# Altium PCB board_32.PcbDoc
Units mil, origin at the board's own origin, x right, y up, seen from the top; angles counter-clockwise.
Board outline 3248.03 x 3149.61 mil, 2 copper layers (Top Layer, Bottom Layer); 42 components, 39 nets, 152 pads, 6 vias.
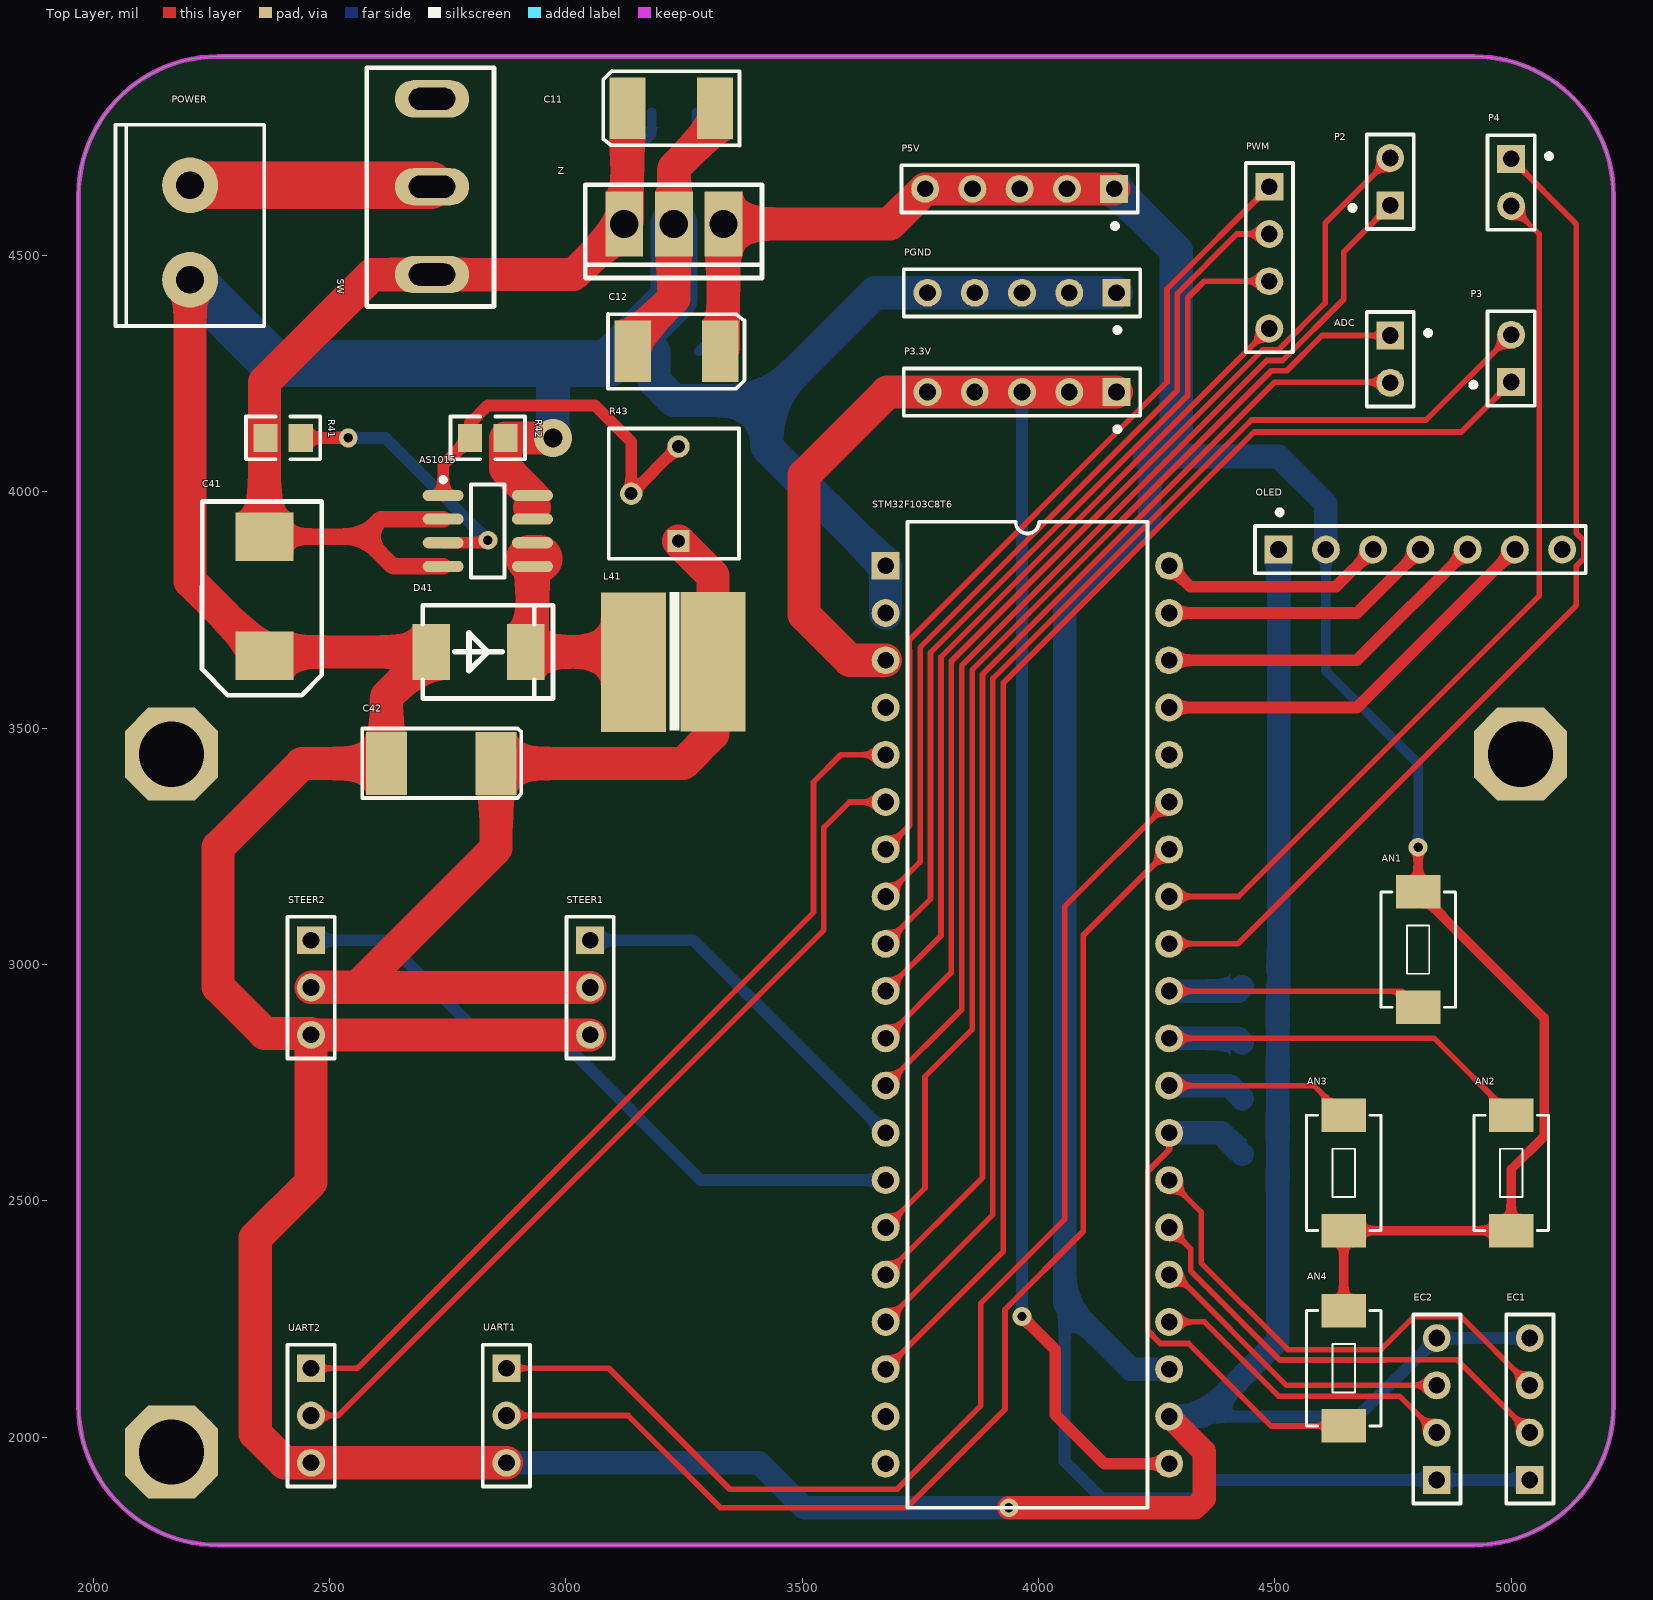
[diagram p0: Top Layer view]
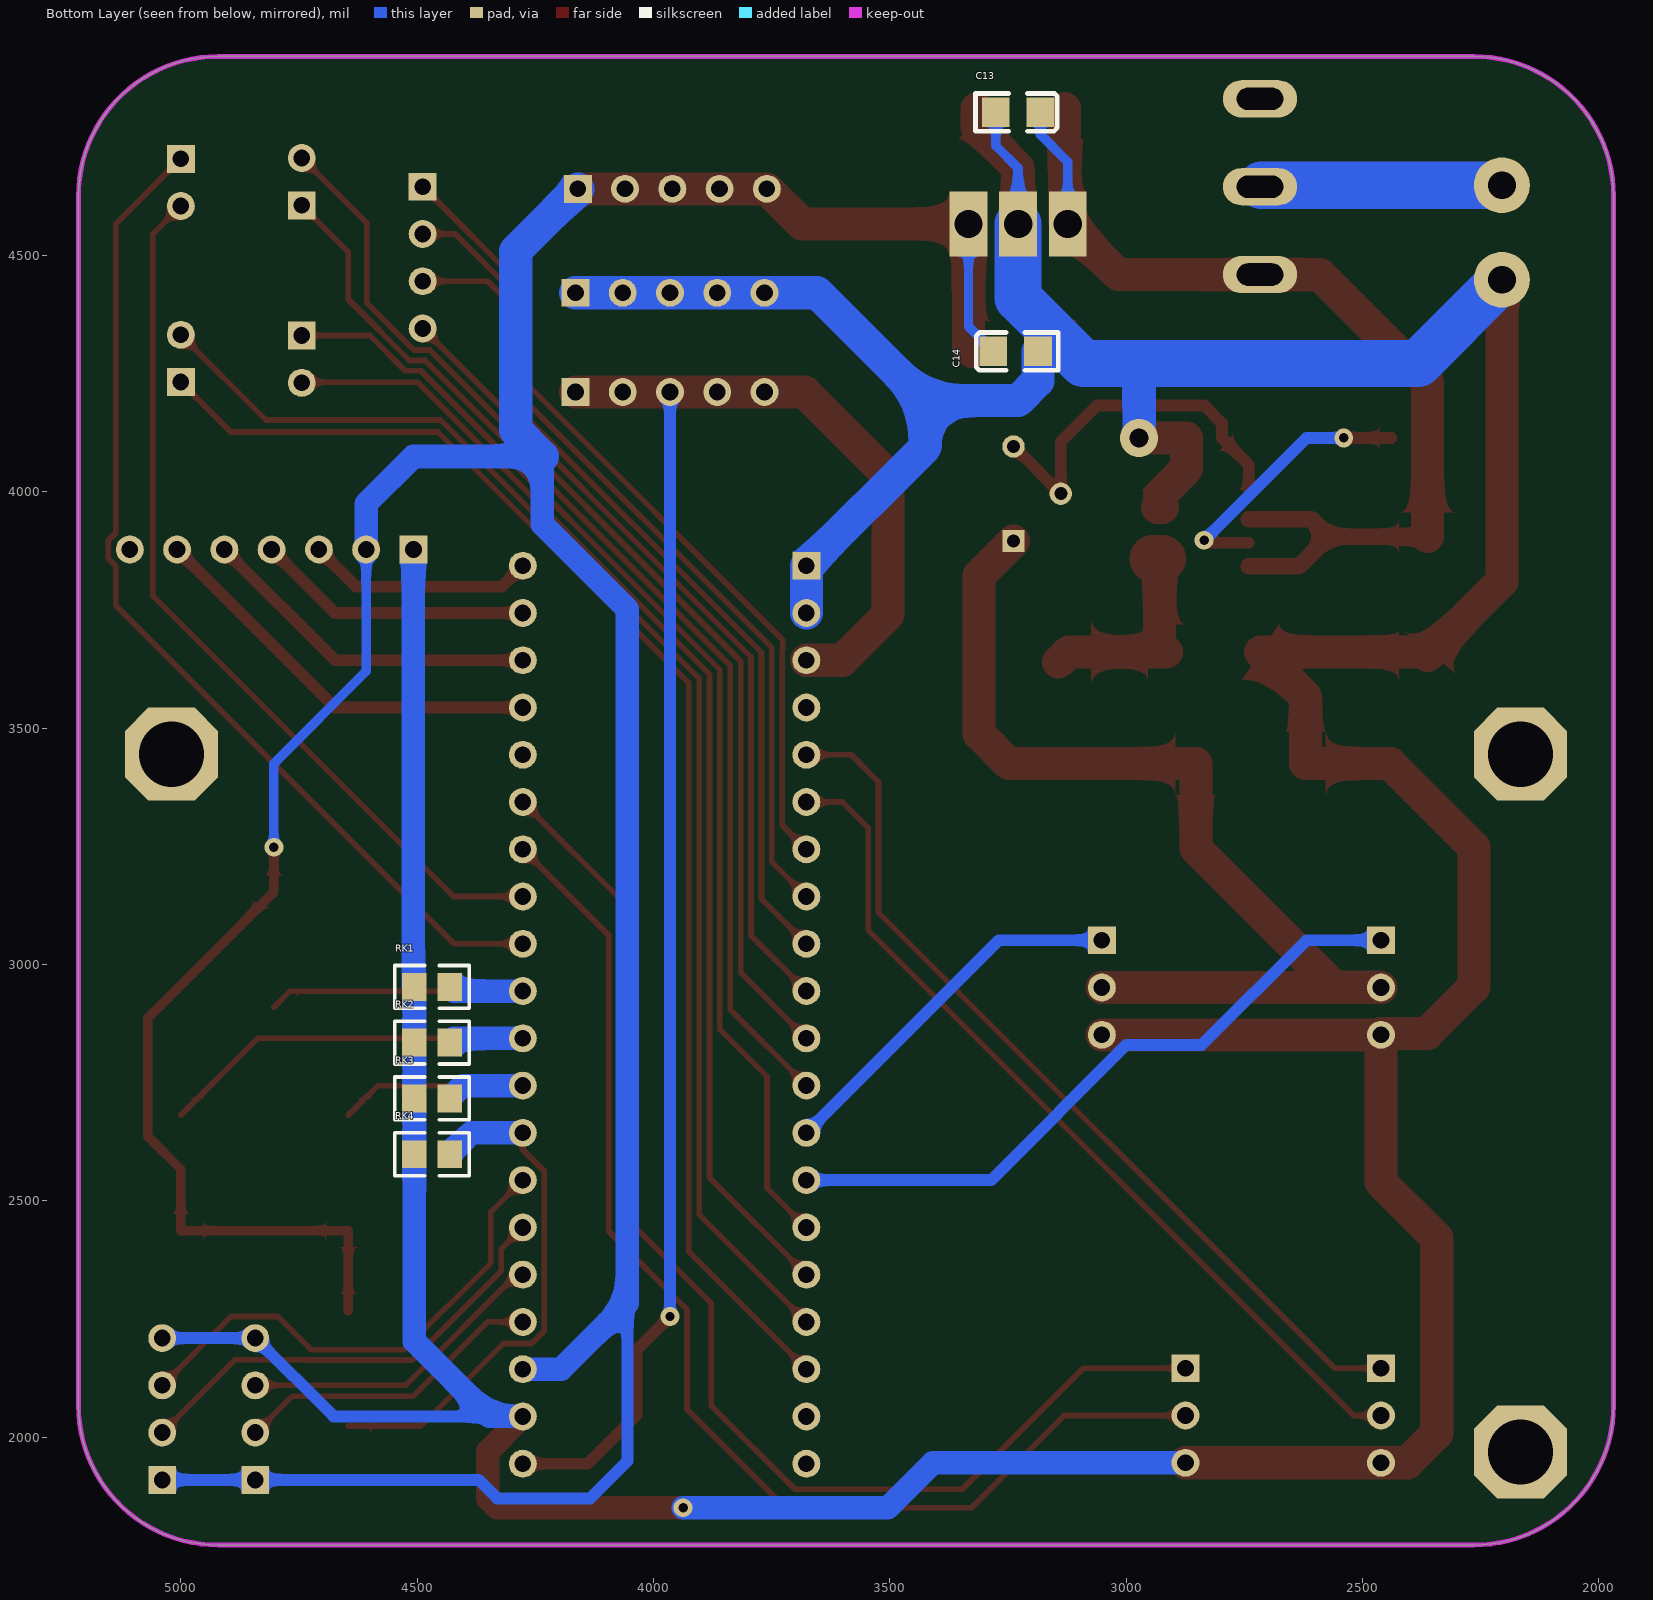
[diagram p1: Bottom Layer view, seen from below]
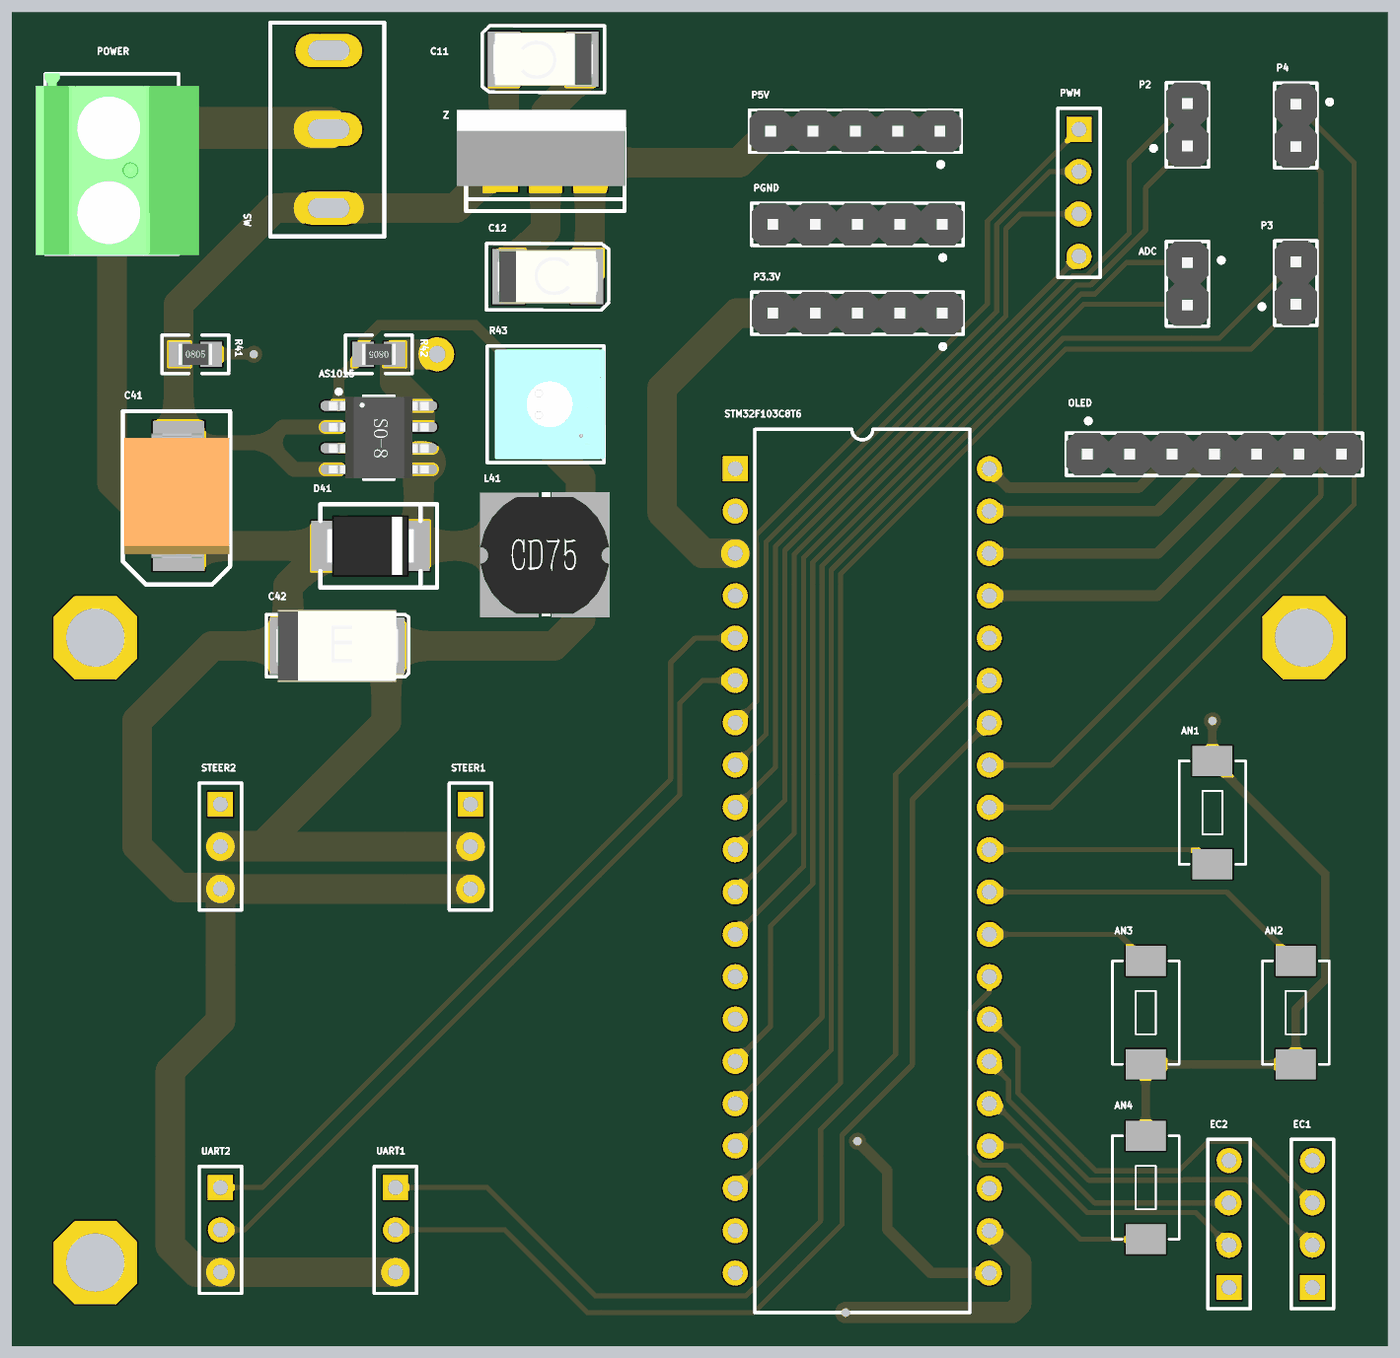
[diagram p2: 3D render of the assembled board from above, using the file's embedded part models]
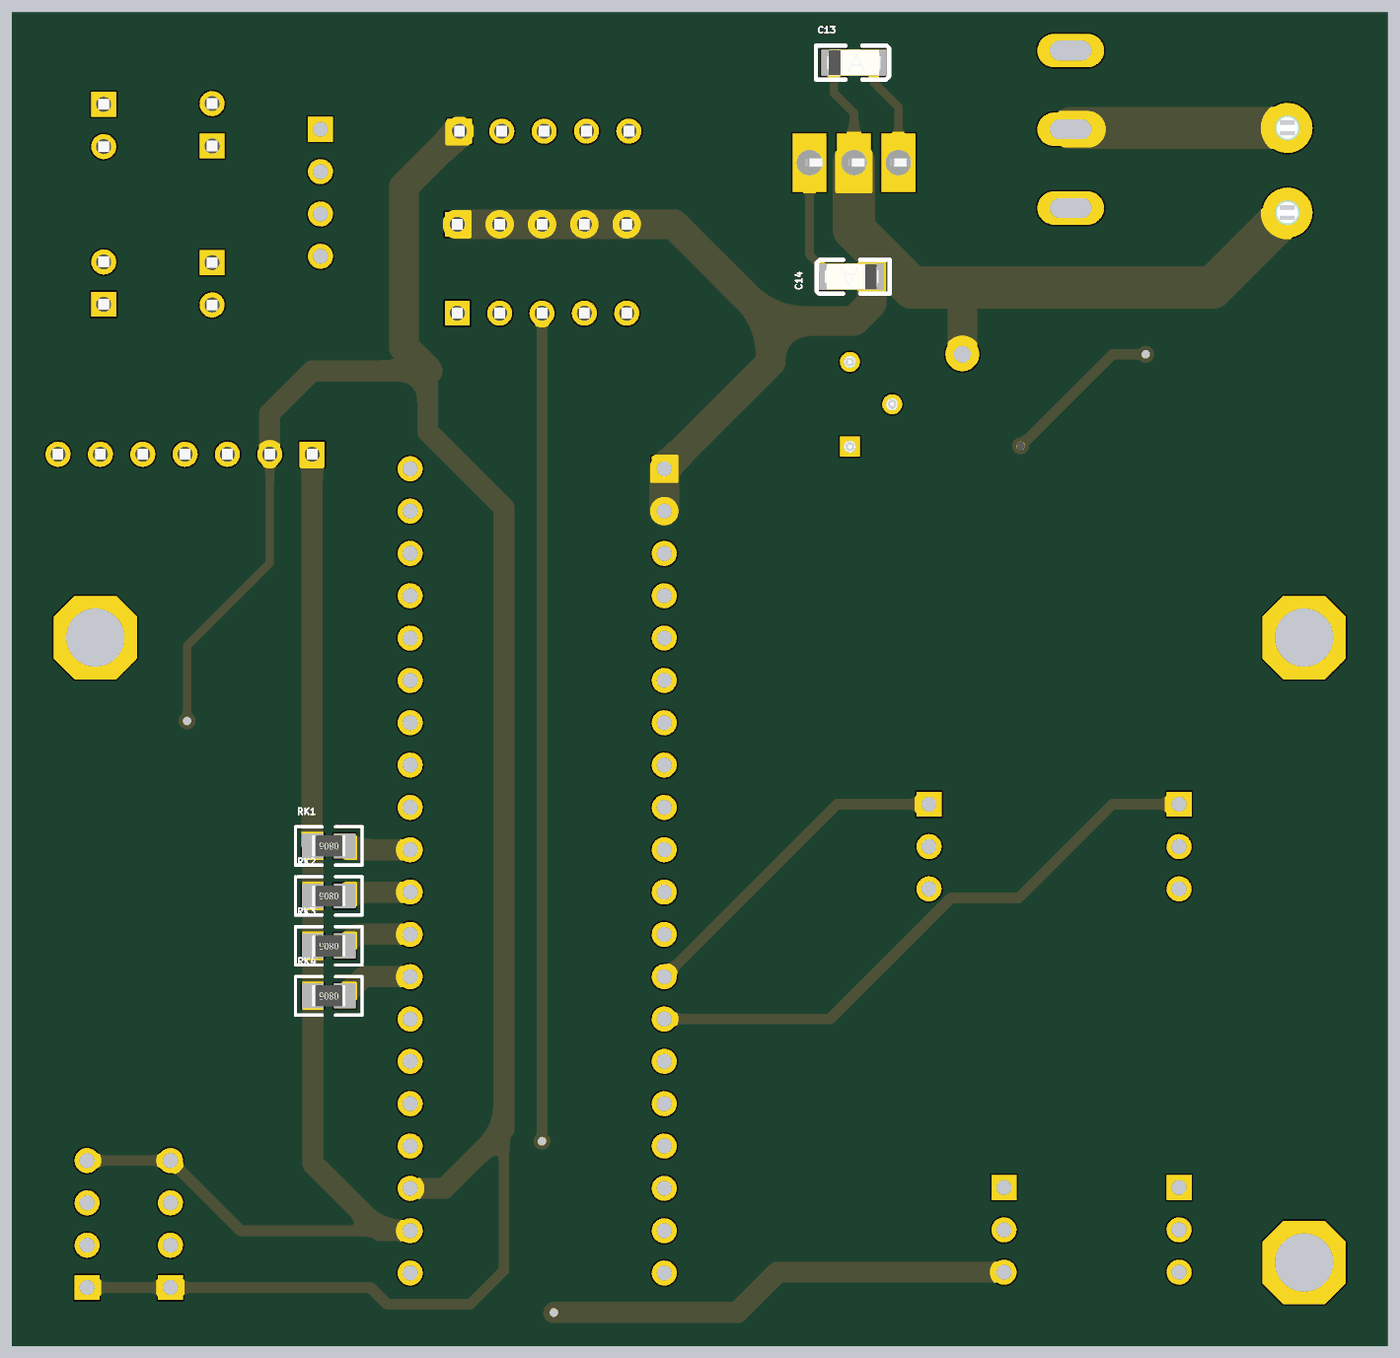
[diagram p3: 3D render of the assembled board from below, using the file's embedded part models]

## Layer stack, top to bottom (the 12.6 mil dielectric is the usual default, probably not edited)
Top Solder: solder mask 0.4, Solder Resist, Dk 3.5
Top Layer: signal copper 1.4
Dielectric 1: dielectric 12.6, FR-4, Dk 4.8
Bottom Layer: signal copper 1.4
Bottom Solder: solder mask 0.4, Solder Resist, Dk 3.5

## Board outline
1968.5,2066.93 1968.5,4625.98 cw(c2263.78,4625.98) 2263.78,4921.26 4921.26,4921.26 cw(c4921.26,4625.98) 5216.54,4625.98 5216.54,2066.93 cw(c4921.26,2066.93) 4921.26,1771.65 2263.78,1771.65 cw(c2263.78,2066.93)

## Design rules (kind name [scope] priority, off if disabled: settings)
Clearance [All] p1: gap=8
Height [All] p1 off: minheight=0 maxheight=1000 prefheight=500
HoleSize [All] p1: absolutevalues=TRUE maxlimit=300 minlimit=1 maxpercent=80.000 minpercent=20.000
PolygonConnect [All] p1: connectstyle=Relief reliefconductorwidth=10 reliefentries=4 polygonreliefangle="90 Angle" airgapwidth=10
RoutingVias [All] p1: holewidth=28 width=50 viastyle="Through Hole" minholewidth=15 minwidth=30 maxholewidth=40 maxwidth=80
SilkToSilkClearance [All] p1 off: silktosilkclearance=10
SilkToSolderMaskClearance [IsPad] p1 off: minsilkscreentomaskgap=10 clearancetoexposedcopper=TRUE
SolderMaskExpansion [All] p1: expansion=4
Width [All] p1: maxlimit=200 minlimit=10 preferedwidth=12
26 further rules are at their usual default settings.

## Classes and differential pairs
component class board_32: ADC AN1 AN2 AN3 AN4 AS1015 C11 C12 C13 C14 C41 C42 D41 EC1 EC2 L41 OLED P2 P3 P3.3V P4 P5V PGND POWER PWM R41 R42 R43 RK1 RK2 RK3 RK4 STEER1 STEER2 STM32F103C8T6 SW UART1 UART2 Z

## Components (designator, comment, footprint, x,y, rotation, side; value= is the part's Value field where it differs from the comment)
ADC "Header 2" HDR1X2 4744.09,4330.71 r270 top
AN1 "Button" SMT4*6.2*4 4803.15,3031.5 r90 top
AN2 "Button" SMT4*6.2*4 5000,2559.06 r270 top
AN3 "Button" SMT4*6.2*4 4645.67,2559.06 r270 top
AN4 "Button" SMT4*6.2*4 4645.67,2145.67 r90 top
AS1015 "AS1015" SOP-8N 2834.65,3917.32 r0 top locked
C11 "Cap Tan C" TAN-C-6032 3222.72,4811.46 r180 top locked
C12 "Cap Tan C" TAN-C-6032 3233.7,4297.4 r0 top locked
C13 "Cap Tan A" TAN-A-3216 3228.35,4803.15 r180 bottom locked
C14 "Cap Tan A" TAN-A-3216 3233.7,4297.4 r0 bottom locked
C41 "Cap Tan E" C7361 2362.2,3779.53 r90 top locked
C42 "Cap Tan E" TAN-E-7361 2736.22,3425.2 r0 top locked
D41 "1N5824" SMB 2814.96,3661.42 r0 top locked
EC1 "Header 4" HDR1X4 5039.37,1909.45 r90 top
EC2 "Header 4" HDR1X4 4842.52,1909.45 r90 top
L41 "Inductor" CD75NP 3228.35,3641.73 r0 top locked
OLED "Header 7" HDR1X7 4507.87,3877.95 r0 top
P2 "Header 2" HDR1X2 4744.09,4606.3 r90 top
P3 "Header 2" HDR1X2 5000,4232.28 r90 top
P3.3V "Header 5" HDR1X5 4164.96,4211.26 r180 top locked
P4 "Header 2" HDR1X2 5000,4704.72 r270 top
P5V "Header 5" HDR1X5 4159.96,4641.26 r180 top locked
PGND "Header 5" HDR1X5 4164.96,4421.26 r180 top locked
POWER "Header 2" 2PIN-5.08A 2204.72,4448.82 r90 top locked
PWM "Header 4" HDR1X4 4488.19,4645.67 r270 top
R41 "Resistor Chip 0805" R0805 2401.57,4114.17 r0 top locked
R42 "Resistor Chip 0805" R0805 2834.65,4114.17 r180 top locked
R43 "RPot" VR_B1 3248.03,3996.06 r90 top locked
RK1 "Resistor Chip 0805" R0805 4468.5,2952.76 r0 bottom
RK2 "Resistor Chip 0805" R0805 4468.5,2834.65 r0 bottom
RK3 "Resistor Chip 0805" R0805 4468.5,2716.54 r0 bottom
RK4 "Resistor Chip 0805" R0805 4468.5,2598.43 r0 bottom
STEER1 "Header 3" HDR1X3 3051.18,3051.18 r270 top locked
STEER2 "Header 3" HDR1X3 2460.63,3051.18 r270 top locked
STM32F103C8T6 "stm32c8t6mini" DIP-40 3976.38,2893.7 r270 top
SW "SW" SW-TO3 2716.54,4645.67 r0 top locked
UART1 "Header 3" HDR1X3 2874.02,2145.67 r270 top
UART2 "Header 3" HDR1X3 2460.63,2145.67 r270 top
Z "LM2940" TO-220E 3228.35,4566.93 r180 top locked
? "Comment" "Screw hexagon 3mm" 2165.35,3444.88 r0 top
? "Comment" "Screw hexagon 3mm" 5019.69,3444.88 r0 top
? "Comment" "Screw hexagon 3mm" 2165.35,1968.5 r0 top

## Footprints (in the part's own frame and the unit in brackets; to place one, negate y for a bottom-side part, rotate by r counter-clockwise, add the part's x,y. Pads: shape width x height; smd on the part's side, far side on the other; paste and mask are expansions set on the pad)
2PIN-5.08A [mm]
  round 3 hole 1.5: 1(0,0) 2(5.08,0)
  silkscreen extent -2.49,-3.99 8.33,4.01, body extent -2.54,-5.2 8.36,4.6, height 14.2
C7361 [mm] "D型"
  rect 2.6x3.1 smd: 1(-3.202,0.007) 2(3.198,0.007)
  silkscreen extent -5.33,-3.07 5.08,3.36, body extent -3.75,-3.05 3.75,3.25, height 3.45
CD75NP [mm]
  rect 3.5x7.5 smd mask+0: 1(-2.174,-0.051) 2(2.101,-0.028)
  silkscreen extent -0.23,-3.72 0.29,3.73, body extent -3.91,-3.57 3.83,3.43, height 5
DIP-40 [mm] "51单片机"
  rect 1.5x1.5 hole 0.9: 1(-24.13,-7.62)
  round 1.5 hole 0.9: 2(-21.59,-7.62) 3(-19.05,-7.62) 4(-16.51,-7.62) 5(-13.97,-7.62) 6(-11.43,-7.62) 7(-8.89,-7.62) 8(-6.35,-7.62) 9(-3.81,-7.62) 10(-1.27,-7.62) 11(1.27,-7.62) 12(3.81,-7.62) 13(6.35,-7.62) 14(8.89,-7.62) 15(11.43,-7.62) 16(13.97,-7.62) 17(16.51,-7.62) 18(19.05,-7.62) 19(21.59,-7.62) 20(24.13,-7.62) 21(24.13,7.62) 22(21.59,7.62) 23(19.05,7.62) 24(16.51,7.62) 25(13.97,7.62) 26(11.43,7.62) 27(8.89,7.62) 28(6.35,7.62) 29(3.81,7.62) 30(1.27,7.62) 31(-1.27,7.62) 32(-3.81,7.62) 33(-6.35,7.62) 34(-8.89,7.62) 35(-11.43,7.62) 36(-13.97,7.62) 37(-16.51,7.62) 38(-19.05,7.62) 39(-21.59,7.62) 40(-24.13,7.62)
  silkscreen extent -26.5,-6.45 26.5,6.45
HDR1X2 [mm] "Connector; Header; 2 Position"
  rect 1.5x1.5 hole 0.9: 1(0,0)
  round 1.5 hole 0.9: 2(2.54,0)
  silkscreen extent -1.27,-1.27 3.81,2.17, body extent -1.27,-1.27 3.81,1.27, height 8.54
HDR1X3 [mm] "Connector; Header; 3 Position"
  rect 1.5x1.5 hole 0.9: 1(0,0)
  round 1.5 hole 0.9: 2(2.54,0) 3(5.08,0)
  silkscreen extent -1.27,-1.27 6.35,1.27
HDR1X4 [mm] "Connector; Header; 4 Position"
  rect 1.5x1.5 hole 0.9: 1(0,0)
  round 1.5 hole 0.9: 2(2.54,0) 3(5.08,0) 4(7.62,0)
  silkscreen extent -1.27,-1.27 8.89,1.27
HDR1X5 [mm] "Connector; Header; 5 Position"
  rect 1.5x1.5 hole 0.9: 1(0,0)
  round 1.5 hole 0.9: 2(2.54,0) 3(5.08,0) 4(7.62,0) 5(10.16,0)
  silkscreen extent -1.27,-1.27 11.43,2.14, body extent -1.27,-1.27 11.43,1.27, height 8.54
HDR1X7 [mm] "Connector; Header; 7 Position"
  rect 1.5x1.5 hole 0.9: 1(0,0)
  round 1.5 hole 0.9: 2(2.54,0) 3(5.08,0) 4(7.62,0) 5(10.16,0) 6(12.7,0) 7(15.24,0)
  silkscreen extent -1.27,-1.27 16.51,2.14, body extent -1.27,-1.27 16.51,1.27, height 8.54
R0805 [mm]
  rect 1.3x1.5 smd: 1(-0.95,0) 2(0.95,0)
  silkscreen extent -2,-1.15 2,1.15, body extent -1,-0.63 1,0.63, height 0.55
"Screw hexagon 3mm" [mm] "screw hole"
  oct 5x5 hole 3.5: 1(0,0)
SMB [mm]
  rect 2x3 smd: 1(-2.54,0) 2(2.54,0)
  silkscreen extent -3,-2.5 4,2.5, body extent -2.65,-1.85 2.65,1.85, height 2.2
SMT4*6.2*4 [mm]
  rect 1.8x2.4 smd: 1(-3.1,0) 2(3.1,0)
  silkscreen extent -3.1,-2 3.1,2, body extent -3.05,-1.95 3.05,1.75, height 2.5
SOP-8N [mm] "SOIC, 8-Leads, Body 4.9x3.9mm, Pitch 1.27mm, IPC Medium Density"
  oval 2.2x0.6 smd: 1(-2.4,1.905) 2(-2.4,0.635) 3(-2.4,-0.635) 4(-2.4,-1.905) 5(2.4,-1.905) 6(2.4,-0.635) 7(2.4,0.635) 8(2.4,1.905)
  silkscreen extent -2.52,-2.5 0.9,2.88, body extent -3,-2.45 3,2.45, height 1.7
SW-TO3 [mm]
  oval 4x2 hole 1.2 slot 2.5 at 0 deg: 1(0,-4.724) 2(0,0) 3(0,4.724)
  silkscreen extent -3.5,-6.43 3.33,6.39, body extent -3.43,-6.36 3.43,6.35, height 28.55
TAN-A-3216 [mm]
  rect 1.5x1.6 smd: 1(-1.2,0) 2(1.2,0)
  silkscreen extent -2.29,-1.02 2.11,1.02, body extent -1.6,-0.8 1.6,0.8, height 1.6
TAN-C-6032 [mm]
  rect 1.95x3.3 smd: 1(-2.35,0) 2(2.35,0)
  silkscreen extent -3.68,-2.01 3.66,2, body extent -3,-1.6 3,1.6, height 2.6
TAN-E-7361 [mm]
  rect 2.2x3.4 smd: 1(-2.95,0) 2(2.95,0)
  silkscreen extent -4.24,-1.85 4.29,1.88, body extent -3.65,-2.15 3.65,2.15, height 4.1
TO-220E [mil]
  rect 80x138 hole 60: 1(105,0) 2(0,0) 3(-105,0)
  silkscreen extent -186,-83 188,114, body extent -190,-125 210,55, height 730
VR_B1 [mm] "Potentiometer; 3 Leads"
  rect 1.2x1.2 hole 0.7: 1(-2.54,0.254)
  round 1.2 hole 0.7: 2(0,2.794) 3(2.54,0.254)
  silkscreen extent -3.5,-3 3.5,4, body extent -3.3,-3.05 3.3,3.55, height 4.4

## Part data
ADC P2 P3 P4 POWER: "Header, 2-Pin"
C11 C12 C13 C14 C41 C42: "Polarized Capacitor (Radial)"
D41: library part 1N4007, "1.0 Ampere General Purpose Rectifier"
EC1 EC2 PWM: "Header, 4-Pin"
OLED: "Header, 7-Pin"
P3.3V P5V PGND: "Header, 5-Pin"
R41 R42 RK1 RK2 RK3 RK4: "Resistor"
R43: "精密可调电阻"
STEER1 STEER2 UART1 UART2: "Header, 3-Pin"
SW: library part 开关三脚大电流
Z: "SOT-223"

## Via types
v1: diameter 40, hole 20, Top Layer to Bottom Layer, tented both sides, 5 vias
v2: diameter 80, hole 40, Top Layer to Bottom Layer, 1 vias

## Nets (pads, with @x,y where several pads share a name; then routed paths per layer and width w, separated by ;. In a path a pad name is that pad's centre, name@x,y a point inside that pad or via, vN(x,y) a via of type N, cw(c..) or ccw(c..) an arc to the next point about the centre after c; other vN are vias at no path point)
3.3V: P3.3V.1 P3.3V.2 P3.3V.3 P3.3V.4 P3.3V.5 STM32F103C8T6.3 STM32F103C8T6.21 | length 3718.6
  Top Layer w25: v1(3964.96,2255.12) 4035.43,2184.65 4035.43,2047.24 4138.98,1943.7 STM32F103C8T6.21
  Top Layer w70: STM32F103C8T6.3 3600.39,3643.7 3503.94,3740.16 3503.94,4035.43 3679.76,4211.26 P3.3V.5 P3.3V.4 P3.3V.3 P3.3V.2 P3.3V.1
  Bottom Layer w25: v1(3964.96,2255.12) P3.3V.3
5V: AN1.2 AN2.2 AN3.2 AN4.2 C12.2 C14.2 EC1.1 EC2.1 OLED.2 P5V.1 P5V.2 P5V.3 P5V.4 P5V.5 STM32F103C8T6.23 Z.3 | length 8274.1
  Top Layer w20: AN4.2 AN3.2 AN2.2 5000,2566.61 5069.74,2636.35 5069.74,2886.95 AN1.2 v1(4803.15,3248.03)
  Top Layer w70: C12.2 3333.35,4304.53 Z.3 3685.63,4566.93 P5V.5 P5V.4 P5V.3 P5V.2 P5V.1
  Bottom Layer w20: C14.2 3333.35,4349.8 Z.3 ; OLED.2 4607.87,3620.47 4803.15,3425.2 v1(4803.15,3248.03)
  Bottom Layer w25: 4055.12,2283.46 4055.12,1948.82 4133.86,1870.08 4330.71,1870.08 4370.08,1909.45 EC2.1 EC1.1
  Bottom Layer w50: STM32F103C8T6.23 4194.88,2143.7 4055.12,2283.46 4055.12,3751.5 4234.96,3931.34 4234.96,4074.8 4507.87,4074.8 4607.87,3974.8 OLED.2
  Bottom Layer w70: P5V.1 4291.34,4509.88 4291.34,4131.18 4234.96,4074.8
6V: C42.2 L41.2 R43.1 STEER1.2 STEER2.2 | length 2206.4
  Top Layer w70: STEER1.2 STEER2.2 2462.2,2952.76 2559.06,2952.76 2852.36,3246.06 C42.2 3248.03,3425.2 3311.05,3488.21 L41.2 3311.05,3823.05 R43.1
A4: P2.1 STM32F103C8T6.12 | length 2324.4
  Top Layer w12: STM32F103C8T6.12 3837.38,2904.7 3837.38,3632.63 4482.89,4278.14 4516.16,4278.14 4645.67,4407.65 4645.67,4507.87 P2.1
A5: P2.2 STM32F103C8T6.11 | length 2324.4
  Top Layer w12: STM32F103C8T6.11 3815.38,2982.7 3815.38,3641.75 4473.77,4300.14 4507.05,4300.14 4606.3,4399.39 4606.3,4568.5 P2.2
A11: P4.2 STM32F103C8T6.33 | length 1895.7
  Top Layer w12: STM32F103C8T6.33 4423.23,3143.7 5059.06,3779.53 5059.06,4545.67 P4.2
A12: P4.1 STM32F103C8T6.32 | length 2172.9
  Top Layer w12: STM32F103C8T6.32 4421.65,3043.7 5137.8,3759.84 5137.8,3843.49 5153.4,3859.09 5153.4,3896.81 5137.8,3912.42 5137.8,4566.93 P4.1
ADC1: ADC.1 STM32F103C8T6.15 | length 2433.1
  Top Layer w12: STM32F103C8T6.15 3759.84,2527.17 3759.84,2762.78 3859.38,2862.32 3859.38,3623.16 4492.36,4256.14 4525.27,4256.14 4599.84,4330.71 ADC.1
ADC2: ADC.2 STM32F103C8T6.16 | length 2474.7
  Top Layer w12: STM32F103C8T6.16 3881.38,2548.7 3881.38,3614.04 4499.62,4232.28 4742.52,4232.28 ADC.2
C14: P3.1 STM32F103C8T6.18 | length 2893.5
  Top Layer w12: STM32F103C8T6.18 3925.38,2392.7 3925.38,3595.82 4456.12,4126.56 4894.28,4126.56 P3.1
C15: P3.2 STM32F103C8T6.17 | length 2853.2
  Top Layer w12: STM32F103C8T6.17 3903.38,2470.7 3903.38,3604.93 4450.4,4151.96 4819.67,4151.96 P3.2
D0: OLED.3 STM32F103C8T6.40 | length 482.5
  Top Layer w25: STM32F103C8T6.40 4320.87,3799.21 4629.13,3799.21 OLED.3
D1: STEER1.1 STM32F103C8T6.13 | length 794
  Bottom Layer w25: STEER1.1 3268.9,3051.18 STM32F103C8T6.13
D2: STEER2.1 STM32F103C8T6.14 | length 1426
  Bottom Layer w25: STEER2.1 2618.11,3051.18 2839.66,2829.63 2999.15,2829.63 3285.08,2543.7 STM32F103C8T6.14
DC: OLED.6 STM32F103C8T6.37 | length 869.9
  Top Layer w25: STM32F103C8T6.37 4673.62,3543.7 OLED.6
DI: OLED.4 STM32F103C8T6.39 | length 587.1
  Top Layer w25: STM32F103C8T6.39 4673.62,3743.7 OLED.4
ECA1: EC1.3 STM32F103C8T6.27 | length 1063.8
  Top Layer w12: STM32F103C8T6.27 4343.91,2476.17 4343.91,2368.69 4527.56,2185.04 4724.41,2185.04 4794.35,2254.98 4893.84,2254.98 EC1.3
ECA2: EC2.3 STM32F103C8T6.25 | length 663.2
  Top Layer w12: STM32F103C8T6.25 4290.16,2343.7 4524.41,2109.45 EC2.3
ECB1: EC1.2 STM32F103C8T6.26 | length 971
  Top Layer w12: STM32F103C8T6.26 4321.91,2398.17 4321.91,2351.32 4510.19,2163.04 4733.52,2163.04 4734.4,2163.92 4884.9,2163.92 EC1.2
ECB2: EC2.2 STM32F103C8T6.24 | length 663.2
  Top Layer w12: STM32F103C8T6.24 4350.79,2243.7 4507.87,2086.61 4763.78,2086.61 4840.94,2009.45 EC2.2
GND: AS1015.7 AS1015.8 C11.1 C12.1 C13.1 C14.1 C41.1 C42.1 D41.1 EC1.4 EC2.4 OLED.1 PGND.1 PGND.2 PGND.3 PGND.4 PGND.5 POWER.1 R42.1 RK1.2 RK2.2 RK3.2 RK4.2 STEER1.3 STEER2.3 STM32F103C8T6.1 STM32F103C8T6.2 STM32F103C8T6.22 UART1.3 UART2.3 Z.2 | length 13232
  Top Layer w50: v1(3937.01,1850.39) 4330.71,1850.39 4350.39,1870.08 4350.39,1969.69 STM32F103C8T6.22
  Top Layer w70: POWER.1 2204.72,3810.67 C41.1 2369.88,3661.42 D41.1 2620.08,3566.54 C42.1 2440.94,3425.2 2263.78,3248.03 2263.78,2952.76 2362.2,2854.33 2460.63,2854.33 STEER2.3 ; UART1.3 UART2.3 2404.72,1945.67 2342.52,2007.87 2342.52,2421.26 2460.63,2539.37 STEER2.3 ; 2923.23,3966.54 2933.07,3966.54 ; AS1015.8 2872.05,4049.41 R42.1 v2(2972.44,4114.17) ; STEER1.3 STEER2.3 ; C12.1 3141.18,4322.28 3228.35,4409.45 Z.2 3228.35,4685.04 3315.24,4771.93 C11.1
  Bottom Layer w20: Z.2 3228.35,4685.04 3275.59,4732.28 C13.1
  Bottom Layer w25: 4346.85,2043.7 4676.77,2043.7 EC2.4 EC1.4
  Bottom Layer w50: UART1.3 3408.66,1945.67 3503.94,1850.39 v1(3937.01,1850.39) ; STM32F103C8T6.22 4346.85,2043.7 4505.91,2202.76 RK4.2 RK3.2 RK2.2 RK1.2 4507.87,2954.72 OLED.1
  Bottom Layer w70: v2(2972.44,4114.17) 2972.44,4271.65 ; C14.1 3186.46,4234.8 3228.35,4192.91 3425.2,4192.91 ; STM32F103C8T6.2 STM32F103C8T6.1 3425.2,4094.88 3425.2,4192.91 ; PGND.1 PGND.2 PGND.3 PGND.4 PGND.5 3653.54,4421.26 3425.2,4192.91
  Bottom Layer w100: POWER.1 2381.89,4271.65 2972.44,4271.65 3090.55,4271.65 3228.35,4409.45 Z.2
KEY1: AN1.1 RK1.1 STM32F103C8T6.31 | length 699.4
  Top Layer w12: STM32F103C8T6.31 4768.9,2943.7 AN1.1
  Bottom Layer w50: STM32F103C8T6.31 4422.05,2943.7 RK1.1
KEY2: AN2.1 RK2.1 STM32F103C8T6.30 | length 949.4
  Top Layer w12: STM32F103C8T6.30 4837.4,2843.7 AN2.1
  Bottom Layer w50: STM32F103C8T6.30 4422.05,2843.7 RK2.1
KEY3: AN3.1 RK3.1 STM32F103C8T6.29 | length 561.2
  Top Layer w12: STM32F103C8T6.29 4583.07,2743.7 AN3.1
  Bottom Layer w50: STM32F103C8T6.29 4403.94,2743.7 RK3.1
KEY4: AN4.1 RK4.1 STM32F103C8T6.28 | length 1109.4
  Top Layer w12: STM32F103C8T6.28 4276.38,2608.09 4230.85,2562.56 4230.85,2224.84 4257.52,2198.17 4317.57,2198.17 4492.13,2023.62 AN4.1
  Bottom Layer w50: STM32F103C8T6.28 4385.83,2643.7 RK4.1
NetAS1015_1: AS1015.1 R42.2 R43.2 R43.3 | length 816.6
  Top Layer w25: AS1015.1 2740.16,4057.09 R42.2 2797.24,4145.67 2834.65,4183.07 3061.02,4183.07 3138.03,4106.06 R43.2 R43.3
NetAS1015_3: AS1015.3 R41.2 | length 574.5
  Top Layer w25: R41.2 v1(2539.37,4114.17) ; AS1015.3 v1@2829.33,3892.32
  Bottom Layer w25: v1(2539.37,4114.17) 2618.11,4114.17 v1(2834.65,3897.64)
NetAS1015_5: AS1015.5 AS1015.6 D41.2 L41.1 | length 474.9
  Top Layer w70: 2929.13,3874.02 AS1015.5 2929.13,3675.59 D41.2 3121.03,3661.42 L41.1
  Top Layer w100: 2923.23,3858.27 2942.91,3858.27
NetPOWER_2: POWER.2 SW.2 | length 1021.8
  Top Layer w100: POWER.2 SW.2@2713.39,4648.82
  Bottom Layer w70: SW.2@2713.39,4648.82 SW.2
  Bottom Layer w100: POWER.2 SW.2@2713.39,4648.82
PWM1: PWM.1 STM32F103C8T6.7 | length 1739.2
  Top Layer w12: STM32F103C8T6.7 3727.38,3294.7 3727.38,3664.83 3726.27,3665.94 3726.27,3686.9 4271.65,4232.28 4271.65,4429.13 PWM.1
PWM2: PWM.2 STM32F103C8T6.8 | length 1778.6
  Top Layer w12: STM32F103C8T6.8 3749.38,3216.7 3749.38,3670.64 4293.65,4214.91 4293.65,4420.02 4419.3,4545.67 PWM.2
PWM3: PWM.3 STM32F103C8T6.9 | length 1818.9
  Top Layer w12: STM32F103C8T6.9 3771.38,3138.7 3771.38,3659.97 4315.65,4204.25 4315.65,4410.91 4350.41,4445.67 PWM.3
PWM4: PWM.4 STM32F103C8T6.10 | length 1738.2
  Top Layer w12: STM32F103C8T6.10 3793.38,3060.7 3793.38,3650.86 PWM.4
RST: OLED.5 STM32F103C8T6.38 | length 728.5
  Top Layer w25: STM32F103C8T6.38 4673.62,3643.7 OLED.5
RX1: STM32F103C8T6.34 UART1.2 | length 2550.9
  Top Layer w12: UART1.2 3131.5,2045.67 3326.77,1850.39 3720.47,1850.39 3928.96,2058.88 3928.96,2270.03 4094.49,2435.56 4094.49,3061.81 STM32F103C8T6.34
RX2: STM32F103C8T6.5 UART2.1 | length 1914.8
  Top Layer w12: UART2.1 2559.06,2145.67 3523.62,3110.24 3523.62,3385.83 3581.5,3443.7 STM32F103C8T6.5
TX1: STM32F103C8T6.35 UART1.1 | length 2625.1
  Top Layer w12: UART1.1 3090.55,2145.67 3346.46,1889.76 3700.79,1889.76 3877.95,2066.93 3877.95,2283.46 4055.12,2460.63 4055.12,3122.44 STM32F103C8T6.35
TX2: STM32F103C8T6.6 UART2.2 | length 1880.3
  Top Layer w12: UART2.2 2518.11,2045.67 3545.62,3073.18 3545.62,3289.72 3599.61,3343.7 STM32F103C8T6.6
VIN: AS1015.2 AS1015.4 C11.2 C13.2 C41.2 R41.1 SW.1 Z.1 | length 2323.1
  Top Layer w35: C41.2 2570.94,3905.43 ; AS1015.4 2634.06,3842.32 2570.94,3905.43 ; AS1015.2 2607.83,3942.32 2570.94,3905.43
  Top Layer w70: C41.2 2361.93,4232.01 2589.59,4459.67 SW.1 3016.09,4459.67 Z.1 3130.2,4573.78 C11.2
  Bottom Layer w20: Z.1 3123.35,4698.15 3181.1,4755.91 C13.2
pads on no net: ?.1 OLED.7 STM32F103C8T6.4 STM32F103C8T6.19 STM32F103C8T6.20 STM32F103C8T6.36 SW.3

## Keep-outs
Keep-Out Layer:
  the board outline again, w10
